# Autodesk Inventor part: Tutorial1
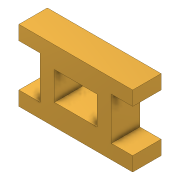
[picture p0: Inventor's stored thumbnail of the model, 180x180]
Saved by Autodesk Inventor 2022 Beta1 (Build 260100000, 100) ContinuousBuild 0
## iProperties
Created: 2021-03
Part Number: Tutorial1
Material: Brass, Soft Yellow
Document SubType Name: Modeling
Designer: ASUS Laptop
Density: 8.47 g/cm^3
Appearance: Brass - Satin
Author: ASUS Laptop
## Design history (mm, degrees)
sketch "Sketch1"
  geometry: L1 (0, 0)-(80, 0); L2 (80, 0)-(80, 10); L3 (80, 10)-(65, 10); L4 (65, 10)-(65, 40); L5 (65, 40)-(80, 40); L6 (80, 40)-(80, 50); L7 (80, 50)-(0, 50); L8 (0, 50)-(0, 40); L9 (0, 40)-(15, 40); L10 (15, 40)-(15, 10); L11 (15, 10)-(0, 10); L12 (0, 0)-(0, 10); L13 (25, 15)-(55, 15); L14 (55, 15)-(55, 35); L15 (55, 35)-(25, 35); L16 (25, 35)-(25, 15)
  constraints: 32 end point, 9 perpendicular, 7 point on line, 2 horizontal, 2 parallel
  dimensions: "d0" = 80 distance between parallel lines of L2 L12; "d1" = 10 distance between parallel lines of L1 L11; "d2" = 10 distance between parallel lines of L9 L7; "d3" = 30 distance between parallel lines of L11 L9; "d4" = 30 distance between parallel lines of L14 L16; "d5" = 10 distance between parallel lines of L10 L16; "d6" = 10 distance between parallel lines of L4 L14; "d7" = 20 distance between parallel lines of L13 L15; "d8" = 15 distance between parallel lines of L13 L1; "d10" = 15 distance between parallel lines of L10 L8
extrude "Extrusion1" new body sketch "Sketch1" distance "d11" = 20; taper "d12" = 0 deg
body "Solid1"
